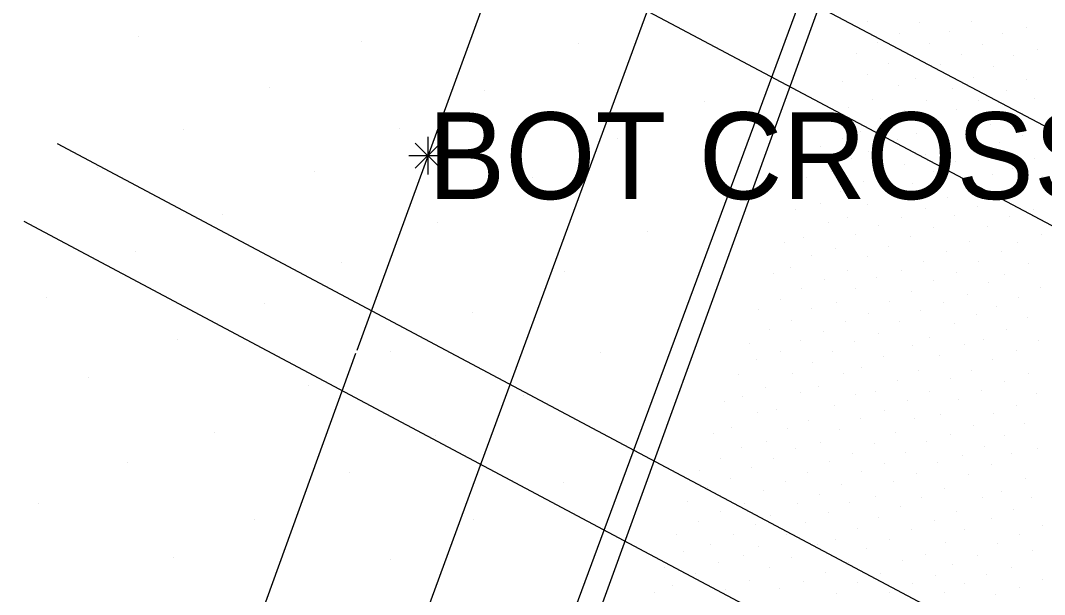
# Model space of a CAD drawing. Extents: x 1729983 to 1730242, y 468641 to 469019.
# Drawn here: x 1730139.58 to 1730160.82, y 468837.66 to 468849.56 of the extents above; entities that cross this region are included whole.
import ezdxf

# ---------------------------------------------------------------- set-up
doc = ezdxf.new("R2010")
doc.units = 0
for name, color, linetype in [('Default', 7, 'Continuous'), ('S_Curb_Type_1', 7, 'Continuous'), ('S_Ground_SpotElevation', 7, 'Continuous'), ('S_Misc_MiscFeature', 7, 'Continuous'), ('S_Misc_MiscItems', 7, 'Continuous'), ('S_Roadway_Edge_Pavement', 7, 'Continuous'), ('S_Roadway_Painted_Lines', 7, 'Continuous'), ('S_Text', 7, 'Continuous')]:
    doc.layers.add(name, color=color, linetype=linetype)

# ---------------------------------------------------------------- blocks, each defined once
blk = doc.blocks.new('POINT_DISPLAY')
at = {"layer": 'Default'}
blk.add_line((0, 0), (0, 0), dxfattribs=at)

msp = doc.modelspace()

# ---------------------------------------------------------------- linework, layer by layer
at = {"layer": 'S_Curb_Type_1'}
msp.add_lwpolyline([(1730095.691, 468641.415), (1730095.909, 468646.136), (1730096.354, 468653.521), (1730096.818, 468653.995), (1730097.198, 468655.848), (1730096.66, 468657.036), (1730097.062, 468660.797), (1730098.243, 468671.757), (1730099.533, 468680.946), (1730101.556, 468692.14), (1730103.524, 468700.629), (1730106.497, 468712.327), (1730109.421, 468721.771), (1730114.404, 468736.003), (1730118.96, 468748.434), (1730124.347, 468762.755), (1730131.22, 468781.92), (1730136.349, 468795.804), (1730142.854, 468813.477), (1730149.849, 468832.496), (1730156.774, 468851.574), (1730163.434, 468869.402), (1730166.697, 468878.04), (1730172.479, 468894.171)], dxfattribs=at)
at = {"layer": 'S_Misc_MiscFeature'}
for p, q in [((1730143.777, 468856.394), (1730171.215, 468841.878)), ((1730170.589, 468840.197), (1730143.174, 468854.759)), ((1730149.971, 468852.065), (1730146.556, 468842.72)), ((1730140.344, 468847.015), (1730167.735, 468832.447)), ((1730167.083, 468830.802), (1730139.654, 468845.393)), ((1730146.533, 468842.658), (1730143.135, 468833.291))]:
    msp.add_line(p, q, dxfattribs=at)
at = {"layer": 'S_Misc_MiscItems'}
for p, q in [((1730148.294, 468846.497), (1730147.77, 468847.021)), ((1730148.294, 468847.021), (1730147.77, 468846.497)), ((1730148.032, 468847.152), (1730148.032, 468846.366)), ((1730148.425, 468846.759), (1730147.639, 468846.759))]:
    msp.add_line(p, q, dxfattribs=at)
at = {"layer": 'S_Roadway_Edge_Pavement'}
msp.add_lwpolyline([(1730169.443, 468886.971), (1730164.503, 468873.715), (1730156.499, 468852.01), (1730147.717, 468828.276), (1730138.371, 468802.607), (1730128.942, 468777.012), (1730117.481, 468745.727), (1730111.874, 468730.709), (1730108.888, 468721.988), (1730105.794, 468711.827), (1730102.94, 468700.647), (1730101.123, 468692.177), (1730099.16, 468681.419), (1730097.818, 468671.805), (1730096.586, 468660.812), (1730096.168, 468657.103), (1730095.956, 468653.708), (1730095.867, 468652.572), (1730095.424, 468646.027), (1730095.252, 468641.367)], dxfattribs=at)
at = {"layer": 'S_Roadway_Painted_Lines'}
msp.add_lwpolyline([(1730094.799, 468656.256), (1730095.17, 468660.96), (1730096.083, 468669.985), (1730097.638, 468680.767), (1730099.581, 468691.95), (1730101.134, 468699.687), (1730104.772, 468714.073), (1730108.651, 468727.01), (1730112.542, 468738.83), (1730119.789, 468759.429), (1730137.203, 468807.807), (1730148.896, 468839.717), (1730160.486, 468871.271), (1730175.799, 468912.851), (1730190.41, 468952.883), (1730200.037, 468978.351)], dxfattribs=at)

# ---------------------------------------------------------------- block references
at = {"layer": 'S_Ground_SpotElevation'}
for p in [(1730157.148, 468849.534), (1730158.228, 468849.531), (1730159.302, 468849.533), (1730160.456, 468849.426), (1730142.033, 468849.23), (1730157.815, 468849.299), (1730158.848, 468849.341), (1730159.956, 468849.291), (1730146.652, 468849.121), (1730151.148, 468849.079), (1730157.356, 468849.111), (1730158.445, 468849.093), (1730159.54, 468849.071), (1730160.688, 468848.958), (1730156.92, 468848.888), (1730158.024, 468848.867), (1730159.105, 468848.854), (1730160.181, 468848.846), (1730157.581, 468848.663), (1730158.666, 468848.656), (1730159.773, 468848.608), (1730156.631, 468848.299), (1730157.142, 468848.438), (1730158.144, 468848.361), (1730159.346, 468848.388), (1730160.449, 468848.332), (1730144.746, 468848.179), (1730149.214, 468848.111), (1730157.798, 468848.219), (1730158.92, 468848.161), (1730160.039, 468848.109), (1730153.772, 468847.879), (1730157.264, 468847.92), (1730158.377, 468847.909), (1730159.457, 468847.895), (1730160.616, 468847.949), (1730156.765, 468847.751), (1730157.924, 468847.701), (1730159.004, 468847.716), (1730160.209, 468847.713), (1730156.399, 468847.607), (1730157.422, 468847.539), (1730158.625, 468847.432), (1730142.954, 468847.31), (1730147.442, 468847.318), (1730157.005, 468847.261), (1730158.17, 468847.225), (1730159.711, 468847.411), (1730151.958, 468847.121), (1730156.639, 468847.122), (1730157.782, 468847.1), (1730158.771, 468847.081), (1730159.283, 468847.198), (1730159.885, 468847.023), (1730160.358, 468847.178), (1730156.172, 468846.95), (1730157.18, 468846.853), (1730159.444, 468846.824), (1730156.823, 468846.692), (1730158.364, 468846.788), (1730158.97, 468846.64), (1730160.618, 468846.704), (1730141.187, 468846.51), (1730145.675, 468846.427), (1730156.407, 468846.423), (1730157.425, 468846.371), (1730157.912, 468846.576), (1730158.519, 468846.423), (1730159.74, 468846.377), (1730160.17, 468846.5), (1730150.201, 468846.312), (1730155.894, 468846.304), (1730157.063, 468846.221), (1730158.081, 468846.183), (1730160.789, 468846.326), (1730156.585, 468846.019), (1730157.597, 468845.979), (1730159.238, 468846.139), (1730160.327, 468846.144), (1730156.17, 468845.77), (1730157.151, 468845.745), (1730158.802, 468845.898), (1730159.927, 468845.883), (1730143.763, 468845.543), (1730155.654, 468845.649), (1730158.349, 468845.668), (1730158.965, 468845.526), (1730159.442, 468845.707), (1730160.6, 468845.651), (1730148.237, 468845.372), (1730156.343, 468845.377), (1730156.743, 468845.473), (1730157.381, 468845.312), (1730157.858, 468845.481), (1730160.107, 468845.488), (1730152.594, 468845.193), (1730156.896, 468845.124), (1730158.524, 468845.279), (1730159.635, 468845.289), (1730160.753, 468845.126), (1730155.44, 468844.961), (1730155.833, 468845.061), (1730157.579, 468844.884), (1730158.035, 468845.084), (1730159.26, 468844.984), (1730160.255, 468844.954), (1730141.973, 468844.768), (1730155.987, 468844.698), (1730156.495, 468844.834), (1730158.799, 468844.763), (1730159.924, 468844.764), (1730146.245, 468844.535), (1730157.143, 468844.662), (1730158.323, 468844.565), (1730159.459, 468844.558), (1730160.5, 468844.527), (1730150.863, 468844.352), (1730155.193, 468844.31), (1730155.557, 468844.45), (1730156.737, 468844.375), (1730157.857, 468844.372), (1730159.008, 468844.329), (1730160.001, 468844.303), (1730156.256, 468844.195), (1730157.346, 468844.226), (1730158.511, 468844.164), (1730159.654, 468844.137), (1730140.123, 468843.825), (1730155.786, 468844.007), (1730156.903, 468844.009), (1730158.062, 468843.95), (1730159.221, 468843.883), (1730160.751, 468844.029), (1730144.639, 468843.694), (1730155.349, 468843.781), (1730156.515, 468843.707), (1730157.612, 468843.732), (1730158.722, 468843.724), (1730159.818, 468843.626), (1730160.278, 468843.815), (1730148.95, 468843.513), (1730154.896, 468843.565), (1730155.98, 468843.591), (1730157.183, 468843.495), (1730158.258, 468843.539), (1730159.42, 468843.461), (1730160.48, 468843.397), (1730155.579, 468843.338), (1730156.695, 468843.323), (1730157.806, 468843.328), (1730158.949, 468843.273), (1730155.109, 468843.152), (1730156.235, 468843.115), (1730157.377, 468843.08), (1730158.445, 468842.988), (1730160.033, 468843.147), (1730142.834, 468842.936), (1730154.705, 468842.872), (1730155.766, 468842.934), (1730156.891, 468842.908), (1730158.089, 468842.817), (1730159.161, 468842.84), (1730159.551, 468842.936), (1730160.706, 468842.933), (1730147.26, 468842.7), (1730151.603, 468842.682), (1730155.339, 468842.703), (1730156.434, 468842.696), (1730157.483, 468842.593), (1730158.649, 468842.618), (1730160.247, 468842.715), (1730154.847, 468842.528), (1730156.007, 468842.477), (1730157.036, 468842.362), (1730159.75, 468842.534), (1730140.991, 468842.16), (1730154.469, 468842.223), (1730155.588, 468842.233), (1730156.664, 468842.242), (1730158.218, 468842.304), (1730158.88, 468842.144), (1730159.3, 468842.309), (1730160.483, 468842.242), (1730145.556, 468841.991), (1730155.037, 468841.959), (1730156.128, 468841.962), (1730157.768, 468842.095), (1730159.986, 468842.082), (1730150.017, 468841.791), (1730154.556, 468841.771), (1730155.759, 468841.844), (1730156.897, 468841.799), (1730157.309, 468841.872), (1730158.428, 468841.873), (1730159.516, 468841.88), (1730160.658, 468841.832), (1730154.177, 468841.655), (1730155.268, 468841.501), (1730156.467, 468841.577), (1730157.982, 468841.672), (1730159.04, 468841.691), (1730160.252, 468841.571), (1730154.862, 468841.431), (1730157.004, 468841.309), (1730157.501, 468841.479), (1730158.132, 468841.299), (1730158.676, 468841.389), (1730159.759, 468841.415), (1730154.335, 468841.121), (1730155.484, 468841.107), (1730155.938, 468841.26), (1730156.576, 468841.076), (1730159.351, 468841.164), (1730160.404, 468841.205), (1730143.613, 468841.009), (1730148.195, 468840.958), (1730153.961, 468840.99), (1730157.74, 468841.017), (1730158.884, 468840.973), (1730159.991, 468840.962), (1730154.546, 468840.7), (1730155.062, 468840.829), (1730155.662, 468840.68), (1730156.177, 468840.812), (1730157.299, 468840.791), (1730158.374, 468840.829), (1730159.578, 468840.727), (1730160.684, 468840.681), (1730154.102, 468840.478), (1730155.209, 468840.482), (1730156.356, 468840.42), (1730156.848, 468840.577), (1730157.947, 468840.597), (1730159.116, 468840.532), (1730160.147, 468840.584), (1730141.794, 468840.396), (1730153.668, 468840.227), (1730154.752, 468840.281), (1730157.512, 468840.369), (1730158.594, 468840.398), (1730159.732, 468840.352), (1730146.416, 468840.179), (1730154.305, 468840.07), (1730155.453, 468840.008), (1730155.915, 468840.197), (1730157.023, 468840.198), (1730158.164, 468840.168), (1730159.248, 468840.139), (1730160.426, 468840.059), (1730150.846, 468839.97), (1730153.833, 468839.866), (1730154.995, 468839.814), (1730156.609, 468839.944), (1730157.691, 468839.993), (1730158.755, 468839.855), (1730159.942, 468839.786), (1730153.411, 468839.593), (1730156.159, 468839.736), (1730157.308, 468839.697), (1730158.281, 468839.676), (1730159.535, 468839.664), (1730160.545, 468839.667), (1730139.952, 468839.549), (1730154.098, 468839.382), (1730154.601, 468839.542), (1730155.696, 468839.545), (1730156.781, 468839.563), (1730157.846, 468839.481), (1730158.999, 468839.385), (1730160.182, 468839.427), (1730144.436, 468839.221), (1730148.98, 468839.22), (1730153.639, 468839.164), (1730155.15, 468839.304), (1730155.872, 468839.15), (1730156.351, 468839.351), (1730157.382, 468839.252), (1730158.539, 468839.188), (1730159.731, 468839.227), (1730154.823, 468839.1), (1730156.936, 468839.023), (1730158.055, 468839.014), (1730159.164, 468838.999), (1730160.779, 468839.081), (1730153.193, 468838.899), (1730154.367, 468838.895), (1730155.468, 468838.898), (1730156.485, 468838.803), (1730157.599, 468838.8), (1730158.774, 468838.728), (1730160.303, 468838.906), (1730153.345, 468838.548), (1730153.89, 468838.699), (1730154.899, 468838.646), (1730156.115, 468838.683), (1730157.128, 468838.615), (1730159.839, 468838.719), (1730160.573, 468838.563), (1730142.752, 468838.424), (1730147.257, 468838.38), (1730154.063, 468838.317), (1730154.576, 468838.469), (1730155.568, 468838.424), (1730156.748, 468838.315), (1730157.87, 468838.353), (1730158.348, 468838.496), (1730159.441, 468838.471), (1730152.945, 468838.216), (1730153.587, 468838.091), (1730155.119, 468838.215), (1730156.28, 468838.12), (1730157.418, 468838.092), (1730158.919, 468838.279), (1730160.136, 468838.222), (1730154.702, 468837.955), (1730155.828, 468837.933), (1730156.939, 468837.909), (1730158.085, 468837.891), (1730158.568, 468838.057), (1730159.172, 468837.881), (1730159.623, 468838.061), (1730160.78, 468837.969), (1730152.724, 468837.688), (1730153.108, 468837.836), (1730154.21, 468837.763), (1730155.333, 468837.78), (1730156.515, 468837.681), (1730157.61, 468837.694), (1730158.747, 468837.701), (1730159.805, 468837.661), (1730160.3, 468837.805)]:
    msp.add_blockref('POINT_DISPLAY', p, dxfattribs=at)

# ---------------------------------------------------------------- texts
at = {"layer": 'S_Text'}
msp.add_text('BOT CROSS BRACES', height=1.8, dxfattribs=at).set_placement((1730148.032, 468845.859))

doc.saveas('drawing.dxf')
